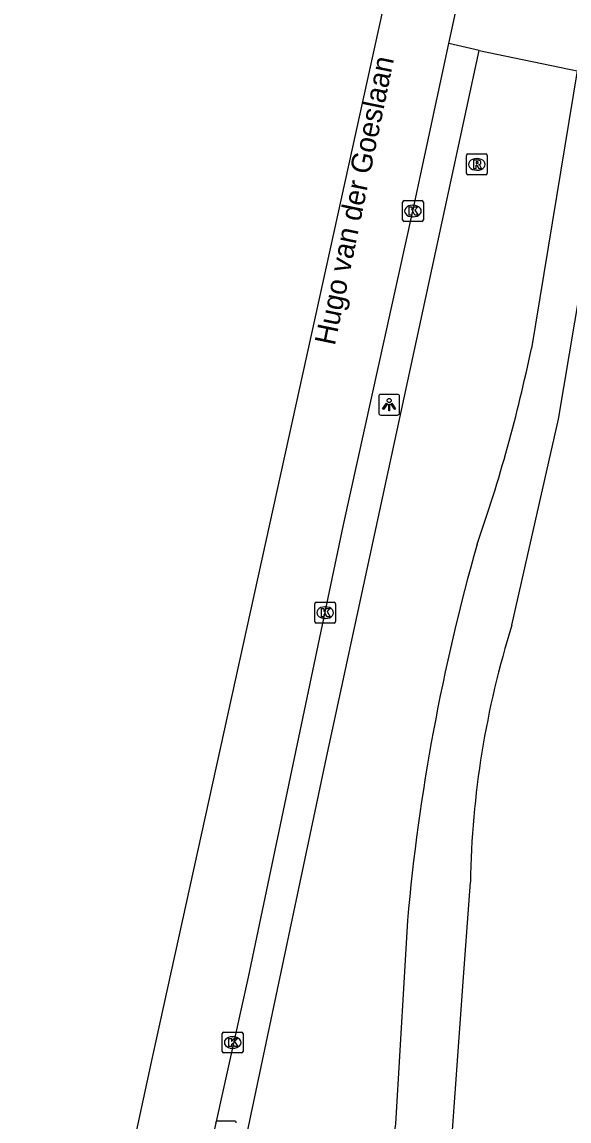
# Model space of a CAD drawing. Extents: x 163046 to 165074, y 382019 to 382874.
# Drawn here: x 163093.6 to 163119.9, y 382743.1 to 382796 of the extents above; entities that cross this region are included whole.
import ezdxf

# ---------------------------------------------------------------- set-up
doc = ezdxf.new("R2010")
doc.units = 0
for name, color, linetype in [('IMGEO_Berm_groen', 7, 'Continuous'), ('IMGEO_Kolk', 7, 'Continuous'), ('IMGEO_Lichtpunt', 7, 'Continuous'), ('IMGEO_Openbare_ruimte_label', 7, 'Continuous'), ('IMGEO_Rijbaan_regionaal_gesloten', 7, 'Continuous'), ('IMGEO_Rioolput', 7, 'Continuous')]:
    doc.layers.add(name, color=color, linetype=linetype)

msp = doc.modelspace()

# ---------------------------------------------------------------- linework, layer by layer
at = {"layer": 'IMGEO_Berm_groen'}
for points in [[(163117.196, 382766.95), (163119.444, 382776.857), (163125.716, 382814.214), (163129.752, 382841.072)], [(163115.63, 382794.599), (163114.168, 382794.935)], [(163100.666, 382724.498), (163108.285, 382760.577), (163115.63, 382794.599)], [(163115.63, 382794.599), (163120.341, 382793.612)], [(163120.341, 382793.612), (163118.136, 382780.262)], [(163113.86, 382735.943), (163114.871, 382750), (163115.2, 382754.577)], [(163112.171, 382752.737), (163112.012, 382750), (163111.604, 382742.954), (163111.027, 382738.885), (163110.259, 382734.848)]]:
    msp.add_lwpolyline(points, dxfattribs=at)
for centre, radius, start, end in [((163045.594, 382795.302), 74.085, 340.7228, 348.28672), ((163210.739, 382743.843), 98.969, 164.16771, 174.84412), ((163159.078, 382753.846), 43.884, 162.6264, 179.0458)]:
    msp.add_arc(centre, radius, start, end, dxfattribs=at)
at = {"layer": 'IMGEO_Kolk'}
for p, q in [((163112.014, 382787.371), (163112.866, 382787.371)), ((163111.939, 382786.445), (163111.939, 382787.297)), ((163112.427, 382787.151), (163112.452, 382787.151)), ((163112.94, 382787.297), (163112.94, 382786.445)), ((163112.866, 382786.371), (163112.014, 382786.371)), ((163112.45, 382786.591), (163112.425, 382786.591)), ((163107.715, 382767.121), (163107.715, 382767.973)), ((163107.79, 382768.047), (163108.642, 382768.047)), ((163108.203, 382767.827), (163108.228, 382767.827)), ((163108.716, 382767.973), (163108.716, 382767.121)), ((163108.226, 382767.267), (163108.201, 382767.267)), ((163108.642, 382767.047), (163107.79, 382767.047)), ((163103.268, 382746.438), (163103.268, 382747.29)), ((163103.343, 382747.364), (163104.195, 382747.364)), ((163103.756, 382747.144), (163103.781, 382747.144)), ((163104.269, 382747.29), (163104.269, 382746.438)), ((163103.779, 382746.584), (163103.754, 382746.584)), ((163104.195, 382746.364), (163103.343, 382746.364))]:
    msp.add_line(p, q, dxfattribs=at)
for points in [[(163112.014, 382787.371), (163112.866, 382787.371)], [(163111.939, 382786.445), (163111.939, 382787.297)], [(163112.26, 382787.071), (163112.383, 382787.071), (163112.383, 382786.92), (163112.513, 382787.071), (163112.677, 382787.071), (163112.531, 382786.92), (163112.684, 382786.671), (163112.532, 382786.671), (163112.447, 382786.835), (163112.383, 382786.768), (163112.383, 382786.671), (163112.26, 382786.671), (163112.26, 382787.071)], [(163112.94, 382787.297), (163112.94, 382786.445)], [(163112.866, 382786.371), (163112.014, 382786.371)], [(163107.715, 382767.121), (163107.715, 382767.973)], [(163107.79, 382768.047), (163108.642, 382768.047)], [(163108.036, 382767.747), (163108.159, 382767.747), (163108.159, 382767.596), (163108.289, 382767.747), (163108.453, 382767.747), (163108.307, 382767.596), (163108.46, 382767.347), (163108.308, 382767.347), (163108.223, 382767.511), (163108.159, 382767.444), (163108.159, 382767.347), (163108.036, 382767.347), (163108.036, 382767.747)], [(163108.716, 382767.973), (163108.716, 382767.121)], [(163108.642, 382767.047), (163107.79, 382767.047)], [(163103.268, 382746.438), (163103.268, 382747.29)], [(163103.343, 382747.364), (163104.195, 382747.364)], [(163104.269, 382747.29), (163104.269, 382746.438)], [(163103.589, 382747.064), (163103.712, 382747.064), (163103.712, 382746.913), (163103.842, 382747.064), (163104.006, 382747.064), (163103.86, 382746.913), (163104.013, 382746.664), (163103.861, 382746.664), (163103.776, 382746.828), (163103.712, 382746.761), (163103.712, 382746.664), (163103.589, 382746.664), (163103.589, 382747.064)], [(163104.195, 382746.364), (163103.343, 382746.364)]]:
    msp.add_lwpolyline(points, dxfattribs=at)
for centre, start, end in [((163112.016, 382787.295), 91.552, 178.448), ((163112.016, 382787.295), 91.552, 178.448), ((163112.864, 382787.295), 1.552, 88.448), ((163112.864, 382787.295), 1.552, 88.448), ((163112.016, 382786.447), 181.552, 268.448), ((163112.016, 382786.447), 181.552, 268.448), ((163112.864, 382786.447), 271.552, 358.448), ((163112.864, 382786.447), 271.552, 358.448), ((163107.792, 382767.971), 91.552, 178.448), ((163107.792, 382767.971), 91.552, 178.448), ((163108.64, 382767.971), 1.552, 88.448), ((163108.64, 382767.971), 1.552, 88.448), ((163107.792, 382767.123), 181.552, 268.448), ((163107.792, 382767.123), 181.552, 268.448), ((163108.64, 382767.123), 271.552, 358.448), ((163108.64, 382767.123), 271.552, 358.448), ((163103.345, 382747.288), 91.552, 178.448), ((163103.345, 382747.288), 91.552, 178.448), ((163104.193, 382747.288), 1.552, 88.448), ((163104.193, 382747.288), 1.552, 88.448), ((163103.345, 382746.44), 181.552, 268.448), ((163103.345, 382746.44), 181.552, 268.448), ((163104.193, 382746.44), 271.552, 358.448), ((163104.193, 382746.44), 271.552, 358.448)]:
    msp.add_arc(centre, 0.0765, start, end, dxfattribs=at)
for centre, major_axis, ratio, start_param, end_param in [((163112.426, 382786.871), (-0.387, 0.002), 0.722429, 4.712389, 7.853982), ((163112.451, 382786.871), (-0.39, 0.002), 0.717154, 1.570796, 4.712389), ((163108.202, 382767.547), (-0.387, 0.002), 0.722429, 4.712389, 7.853982), ((163108.227, 382767.547), (-0.39, 0.002), 0.717154, 1.570796, 4.712389), ((163103.755, 382746.864), (-0.387, 0.002), 0.722429, 4.712389, 7.853982), ((163103.78, 382746.864), (-0.39, 0.002), 0.717154, 1.570796, 4.712389)]:
    msp.add_ellipse(centre, major_axis=major_axis, ratio=ratio, start_param=start_param, end_param=end_param, dxfattribs=at)
at = {"layer": 'IMGEO_Lichtpunt'}
for p, q in [((163110.795, 382777.956), (163110.795, 382777.149)), ((163110.795, 382777.956), (163110.795, 382777.149)), ((163111.697, 382778.051), (163110.889, 382778.051)), ((163111.697, 382778.051), (163110.889, 382778.051)), ((163111.791, 382777.149), (163111.791, 382777.956)), ((163111.791, 382777.149), (163111.791, 382777.956)), ((163110.889, 382777.055), (163111.697, 382777.055)), ((163110.889, 382777.055), (163111.697, 382777.055)), ((163103.85, 382743.086), (163103.042, 382743.086)), ((163103.85, 382743.086), (163103.042, 382743.086))]:
    msp.add_line(p, q, dxfattribs=at)
for points in [[(163111.169, 382777.62), (163111.208, 382777.592), (163111.02, 382777.33), (163110.982, 382777.357), (163111.169, 382777.62)], [(163111.271, 382777.572), (163111.318, 382777.572), (163111.318, 382777.25), (163111.271, 382777.25), (163111.271, 382777.572)], [(163111.381, 382777.592), (163111.419, 382777.619), (163111.606, 382777.357), (163111.567, 382777.329), (163111.381, 382777.592)]]:
    msp.add_lwpolyline(points, dxfattribs=at)
msp.add_circle((163111.294, 382777.754), 0.0994, dxfattribs=at)
for centre, start, end in [((163110.889, 382777.956), 90, 180), ((163110.889, 382777.956), 90, 180), ((163111.697, 382777.956), 0, 90), ((163111.697, 382777.956), 0, 90), ((163110.889, 382777.149), 180, 270), ((163110.889, 382777.149), 180, 270), ((163111.697, 382777.149), 270, 0), ((163111.697, 382777.149), 270, 360), ((163103.042, 382742.991), 90, 180), ((163103.042, 382742.991), 90, 180), ((163103.85, 382742.991), 0, 90), ((163103.85, 382742.991), 0, 90)]:
    msp.add_arc(centre, 0.0946, start, end, dxfattribs=at)
at = {"layer": 'IMGEO_Rijbaan_regionaal_gesloten'}
for points in [[(163093.637, 382717.052), (163099.919, 382746.137), (163106.108, 382774.281), (163122.779, 382850.09)], [(163114.168, 382794.935), (163114.915, 382798.417), (163114.939, 382798.525)], [(163098.978, 382724.989), (163104.532, 382750), (163109.102, 382771.769), (163112.439, 382786.872), (163114.168, 382794.935)]]:
    msp.add_lwpolyline(points, dxfattribs=at)
at = {"layer": 'IMGEO_Rioolput'}
for p, q in [((163115.01, 382788.69), (163115.01, 382789.542)), ((163115.085, 382789.616), (163115.937, 382789.616)), ((163116.011, 382789.542), (163116.011, 382788.69)), ((163115.498, 382789.396), (163115.523, 382789.396)), ((163115.937, 382788.616), (163115.085, 382788.616)), ((163115.521, 382788.836), (163115.496, 382788.836))]:
    msp.add_line(p, q, dxfattribs=at)
for points in [[(163115.01, 382788.69), (163115.01, 382789.542)], [(163115.085, 382789.616), (163115.937, 382789.616)], [(163116.011, 382789.542), (163116.011, 382788.69)], [(163115.599, 382789.314), (163115.347, 382789.316), (163115.347, 382788.916)], [(163115.347, 382788.916), (163115.471, 382788.916), (163115.471, 382789.078), (163115.482, 382789.078)], [(163115.525, 382789.235), (163115.471, 382789.235), (163115.471, 382789.154)], [(163115.471, 382789.154), (163115.523, 382789.154)], [(163115.529, 382789.049), (163115.6, 382788.916), (163115.74, 382788.916), (163115.675, 382789.042)], [(163115.937, 382788.616), (163115.085, 382788.616)]]:
    msp.add_lwpolyline(points, dxfattribs=at)
for centre, radius, start, end in [((163115.087, 382789.54), 0.0765, 91.552, 178.448), ((163115.087, 382789.54), 0.0765, 91.552, 178.448), ((163115.935, 382789.54), 0.0765, 1.552, 88.448), ((163115.935, 382789.54), 0.0765, 1.552, 88.448), ((163115.481, 382789.025), 0.0533, 26.0293, 88.6989), ((163115.507, 382789.343), 0.19, 274.7715, 282.9687), ((163115.531, 382789.139), 0.0964, 77.0061, 93.1865), ((163115.545, 382789.196), 0.0378, 276.6634, 79.6772), ((163115.598, 382789.204), 0.109, 350.3612, 89.416), ((163115.596, 382789.204), 0.112, 277.5842, 350.9817), ((163115.58, 382788.989), 0.108, 29.5134, 73.7905), ((163115.087, 382788.692), 0.0765, 181.552, 268.448), ((163115.087, 382788.692), 0.0765, 181.552, 268.448), ((163115.935, 382788.692), 0.0765, 271.552, 358.448), ((163115.935, 382788.692), 0.0765, 271.552, 358.448)]:
    msp.add_arc(centre, radius, start, end, dxfattribs=at)
for centre, major_axis, ratio, start_param, end_param in [((163115.497, 382789.116), (-0.387, 0.002), 0.722429, 4.712389, 7.853982), ((163115.522, 382789.116), (-0.39, 0.002), 0.717154, 1.570796, 4.712389)]:
    msp.add_ellipse(centre, major_axis=major_axis, ratio=ratio, start_param=start_param, end_param=end_param, dxfattribs=at)

# ---------------------------------------------------------------- texts
at = {"layer": 'IMGEO_Openbare_ruimte_label'}
msp.add_text('Hugo van der Goeslaan', height=1, rotation=78.3416, dxfattribs=at).set_placement((163108.678, 382780.367))

doc.saveas('drawing.dxf')
